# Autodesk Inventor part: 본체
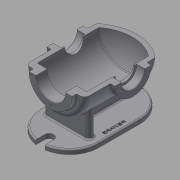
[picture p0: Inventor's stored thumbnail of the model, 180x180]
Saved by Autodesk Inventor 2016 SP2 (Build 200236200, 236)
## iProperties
Created: 2016-02
Part Number: 본체
Material: 알루미늄 6061
Document SubType Name: Modeling
Designer: mduedu
Density: 2.71 g/cm^3
Appearance: 기본값
Author: mduedu
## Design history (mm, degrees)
sketch "스케치2"
  geometry: L1 (0, 90)-(0, -90); L2 (65, -65.993)-(65, 90); L3 (65, 90)-(0, 90); A1 r 100 centre (0, 10) between (0, -90) and (65, -65.993); 2 further points
  constraints: 6 end point, 2 point on circle, 1 centre point, 1 coincident, 1 horizontal, 1 midpoint, 1 parallel, 1 point on line, 1 vertical
  dimensions: "d3" = 180 distance of L1.start L1.end; "d5" = 130 diameter of L2 L1; "d6" = 100 radius of A1
revolve "회전1" sketch "스케치2" stored, may be unused: angle "d7" = 90 deg
sketch "스케치3"
  geometry: C1 r 47.5 at (0, 0); 1 further point
  constraints: 1 centre point, 1 coincident
  dimensions: "d8" = 95 diameter of C1
extrude "돌출2" join sketch "스케치3" distance "d10" = 10; taper "d11" = 0 deg
sketch "스케치5"
  geometry: L1 (47.5, 100)-(47.5, 90) reference; L2 (47.5, 90)-(65, 90) reference; L3 (65, 90)-(65, -65.993) reference; L4 (-65, -65.993)-(-65, 90) reference; L5 (-65, 90)-(-47.5, 90) reference; L6 (-47.5, 90)-(-47.5, 100) reference; L7 (-47.5, 100)-(47.5, 100) reference; L8 (55, 75)-(55, -61.239); L9 (0, 75)-(55, 75); L10 (0, 75)-(0, -80); A1 r 100 centre (0, 10) between (-65, -65.993) and (0, -90) reference; A2 r 100 centre (0, 10) between (0, -90) and (65, -65.993) reference; A3 r 90 centre (0, 10) between (0, -80) and (55, -61.239); 1 further point
  constraints: 6 end point, 2 point on circle, 1 centre point, 1 parallel, 1 perpendicular, 1 point on line, 1 vertical
  dimensions: "d13" = 10 distance between parallel lines of L3 L8; "d14" = 10 radial gap between concentric circles of A3 A1; "d15" = 15 distance between parallel lines of L9 L2
revolve "회전2" sketch "스케치5" stored, may be unused: angle "d16" = 90 deg
hole "구멍1" diameter "d19" = 65; stored, may be unused: countersink angle "d23" = 90 deg, drill point angle "d25" = 118 deg; dims "d17" = 10, "d18" = 10, "d20" = 6, "d21" = 4, "d22" = 2, "d24" = 8
node "작업 평면1"
sketch "스케치6"
  geometry: L1 (47.5, 100)-(-47.5, 100) reference; C1 r 40 at (0, -7); 1 further point
  constraints: 1 centre point, 1 vertical alignment
  dimensions: "d27" = 80 diameter of C1; "d29" = 107 distance from line of C1.centre L1
extrude "돌출3" join sketch "스케치6" stored distance "d30" = 10; taper "d31" = 0 deg
hole "구멍2" diameter "d34" = 42; stored, may be unused: countersink angle "d38" = 90 deg, drill point angle "d40" = 118 deg; dims "d32" = 10, "d33" = 10, "d35" = 6, "d36" = 52, "d37" = 18, "d39" = 8
sketch "스케치7" dims "d41" = 65
  geometry: C1 r 40 at (0, 0) reference; 3 further points
  constraints: 2 vertical alignment, 1 coincident, 2 other
hole "구멍3" sketch "스케치7" at (0, 32.5) diameter "d43" = 3.242; stored, may be unused: countersink angle "d47" = 90 deg, drill point angle "d49" = 118 deg; dims "d44" = 11, "d45" = 13, "d46" = 18, "d48" = 13
sketch "스케치8" dims "d53" = 80
  geometry: 3 further points
  constraints: 2 vertical alignment, 1 coincident, 2 other
hole "구멍4" sketch "스케치8" at (0, -40) diameter "d56" = 3.242; stored, may be unused: countersink angle "d60" = 90 deg, drill point angle "d62" = 118 deg; dims "d57" = 11, "d58" = 13, "d59" = 18, "d61" = 13
fillet "모깎기1" dims "d66" = 10
fillet "모깎기2" dims "d67" = 3
fillet "모깎기3" dims "d68" = 0.3
chamfer "모따기1" distance "d69" = 1; stored, may be unused: second distance "d70" = 2, angle "d71" = 45 deg
node "작업 평면5"
sketch "스케치10"
  geometry: L1 (-50, 66)-(50, 66); L2 (50, 66)-(50, 50); L3 (50, 50)-(-50, 50); L4 (-50, 50)-(-50, 66); 2 further points
  constraints: 8 end point, 2 horizontal, 2 vertical, 1 midpoint, 1 vertical alignment
  dimensions: "d177" = 50 distance from line of L3 point (0, 0); "d178" = 100 distance of L1.start L1.end; "d179" = 16 distance of L3.end L1.start
extrude "돌출5" join sketch "스케치10" stored distance "d84" = 10; taper "d85" = 0 deg
sketch "스케치21" dims "d180" = 220, "d182" = 130
  geometry: L1 (65, 58)-(-65, 58); L2 (-65, 58)-(-65, -32); L3 (-65, -32)-(65, -32); L4 (65, -32)-(65, 58); L5 (50, 50)-(50, 66) reference; 4 further points
  constraints: 8 end point, 3 horizontal alignment, 3 midpoint, 2 parallel, 1 horizontal, 1 perpendicular, 1 vertical alignment, 4 other
extrude "돌출13" join sketch "스케치21" distance "d183" = 10; taper "d184" = 0 deg
sketch "스케치11"
  geometry: L1 (-65, 80)-(-65, -61.239) reference; L2 (-100, -97)-(-100, -32) reference; L3 (-65, -42.793)-(-100, -63); L4 (-100, -97)-(-110, -97) reference; 1 further point
  constraints: 2 end point, 2 point on line
  dimensions: "d185" = 34 distance from line of L3.end L4; "d186" = 120 deg angle of L2 L3
feature "리브1" sketch "스케치11" dims "d88" = 1, "d89" = 16, "d90" = 0, "d91" = 0, "d92" = 1, "d93" = 1
fillet "모깎기12"
fillet "모깎기13"
fillet "모깎기16" dims "d167" = 3
fillet "모깎기18"
fillet "모깎기17" dims "d168" = 3
fillet "모깎기19" dims "d187" = 3
node "작업 평면6"
sketch "스케치19"
  geometry: L1 (75, -47)-(75, 33) reference; L2 (-75, -47)-(-75, 33) reference; L3 (75, -7)-(-75, -7); C1 r 22.5 at (0, -7); 1 further point
  constraints: 3 midpoint, 2 end point, 1 centre point
  dimensions: "d149" = 45 diameter of C1
extrude "돌출11" join sketch "스케치19" stored distance "d150" = 10; taper "d151" = 0 deg
hole "구멍6" diameter "d154" = 33.376; stored, may be unused: countersink angle "d158" = 90 deg, drill point angle "d160" = 118 deg; dims "d155" = 6, "d156" = 4, "d157" = 2, "d159" = 8, "d190" = 10, "d191" = 10
fillet "모깎기11" dims "d161" = 3
chamfer "모따기3" distance "d164" = 1; stored, may be unused: second distance "d165" = 2, angle "d166" = 45 deg
node "작업 평면9"
  node "작업 평면8"
sketch "스케치22" dims "d189" = 20
  geometry: L1 (-10, -123)-(10, -123); L2 (10, -123)-(10, -103); L3 (10, -103)-(-10, -103); L4 (-10, -103)-(-10, -123); A1 r 65 centre (0, -58) between (-65, -58) and (65, -58) reference; 2 further points
  constraints: 8 end point, 2 parallel, 1 horizontal, 1 horizontal alignment, 1 midpoint, 1 perpendicular, 1 tangent, 1 vertical alignment, 2 other
  dimensions: "d193" = 30 dimension on L1
extrude "돌출14" cut sketch "스케치22" stored distance "d194" = 10; taper "d195" = 0 deg
fillet "모깎기21" dims "d196" = 3
feature "분할1"
sketch "스케치23"
  geometry: L1 (-65, 32)-(-65, -58) reference; L2 (65, -58)-(65, 32) reference; L3 (-65, -13)-(65, -13); 2 further points
  constraints: 2 end point, 2 midpoint, 1 point on line, 1 other
  dimensions: "d197" = 12 distance from line of point (53, -13) L2
feature "엠보싱2" sketch "스케치23" dims "d8" = 95, "d198" = 0.5, "d199" = 0
node "솔리드2"
pattern_circular "원형 패턴1" dims angle "d51" = 360 deg
mirror "대칭1"
pattern_circular "원형 패턴2" dims angle "d64" = 360 deg
mirror "대칭3"
node "절단 모서리 투영1"
other parameters: "d26" = 75, "d136" = 175
